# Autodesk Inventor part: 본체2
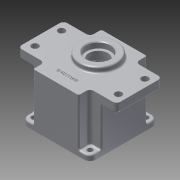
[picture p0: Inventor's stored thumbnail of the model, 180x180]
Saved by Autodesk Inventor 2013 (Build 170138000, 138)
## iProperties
Created: 2015-07
Part Number: 본체2
Material: 알루미늄 6061
Document SubType Name: Modeling
Designer: user
Density: 2.71 g/cm^3
Mass: 706.146 g
Surface Area: 672.799 cm^2
Volume: 260.571 cm^3
Author: user
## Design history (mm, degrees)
sketch "스케치1"
  geometry: L1 (-65, -30)-(65, -30); L2 (65, -30)-(65, 30); L3 (65, 30)-(-65, 30); L4 (-65, 30)-(-65, -30); L5 (-65, -30)-(65, 30); L6 (65, -30)-(-65, 30); 1 further point
  constraints: 12 end point, 2 midpoint, 2 parallel, 1 horizontal, 1 perpendicular
  dimensions: "d0" = 130 distance of L3.end L2.end; "d1" = 60 distance of L2.end L1.end
extrude "돌출1" new body sketch "스케치1" distance "d2" = 12; taper "d3" = 0 deg
sketch "스케치2"
  geometry: L1 (-30, -45)-(30, -45); L2 (30, -45)-(30, 45); L3 (30, 45)-(-30, 45); L4 (-30, 45)-(-30, -45); L5 (-30, -45)-(30, 45); L6 (30, -45)-(-30, 45); 1 further point
  constraints: 12 end point, 2 midpoint, 2 parallel, 1 horizontal, 1 perpendicular
  dimensions: "d4" = 60 distance of L3.end L2.end; "d5" = 90 distance of L2.end L1.end
extrude "돌출2" join sketch "스케치2" distance "d6" = 70; taper "d7" = 0 deg
sketch "스케치3"
  geometry: L1 (-30, -45)-(30, -45) reference; L2 (30, -45)-(30, 45) reference; L3 (30, 45)-(-30, 45) reference; L4 (-30, 45)-(-30, -45) reference; L5 (-45, -45)-(45, -45); L6 (45, -45)-(45, 45); L7 (45, 45)-(-45, 45); L8 (-45, 45)-(-45, -45); L9 (-45, -45)-(45, 45); L10 (45, -45)-(-45, 45); 1 further point
  constraints: 12 end point, 2 midpoint, 2 parallel, 1 horizontal, 1 perpendicular
  dimensions: "d8" = 90 distance of L7.end L6.end; "d9" = 90 distance of L6.end L5.end
extrude "돌출3" join sketch "스케치3" distance "d10" = 7; taper "d11" = 0 deg
fillet "모깎기1" dims "d12" = 5
fillet "모깎기2" dims "d13" = 8
sketch "스케치4"
  geometry: L1 (-45, -30)-(45, -30); L2 (45, -30)-(45, 30); L3 (45, 30)-(-45, 30); L4 (-45, 30)-(-45, -30); L5 (-45, -30)-(45, 30); L6 (45, -30)-(-45, 30); 1 further point
  constraints: 12 end point, 2 midpoint, 2 parallel, 1 horizontal, 1 perpendicular
  dimensions: "d14" = 90 distance of L3.end L2.end; "d15" = 60 distance of L2.end L1.end
extrude "돌출4" join sketch "스케치4" distance "d16" = 70; taper "d17" = 0 deg
fillet "모깎기3" dims "d18" = 5
fillet "모깎기4" dims "d19" = 2
fillet "모깎기5" dims "d20" = 2
fillet "모깎기6" dims "d21" = 2
sketch "스케치5"
  geometry: L1 (-37, -37)-(37, -37); L2 (37, -37)-(37, 37); L3 (37, 37)-(-37, 37); L4 (-37, 37)-(-37, -37); L5 (-37, -37)-(37, 37); L6 (37, -37)-(-37, 37); C1 r 3.5 at (37, 37); C2 r 3.5 at (37, -37); C3 r 3.5 at (-37, 37); C4 r 3.5 at (-37, -37); 1 further point
  constraints: 12 end point, 4 centre point, 4 coincident, 2 midpoint, 2 parallel, 1 horizontal, 1 perpendicular
  dimensions: "d22" = 74 distance of L3.end L2.end; "d23" = 74 distance of L2.end L1.end; "d24" = 7 diameter of C1; "d25" = 7 diameter of C2; "d26" = 7 diameter of C3; "d27" = 7 diameter of C4
extrude "돌출5" cut sketch "스케치5" distance "d28" = 70; taper "d29" = 0 deg
sketch "스케치6"
  geometry: L1 (-55, -17.5)-(55, -17.5); L2 (55, -17.5)-(55, 17.5); L3 (55, 17.5)-(-55, 17.5); L4 (-55, 17.5)-(-55, -17.5); L5 (-55, -17.5)-(55, 17.5); L6 (55, -17.5)-(-55, 17.5); C1 r 4.5 at (55, 17.5); C2 r 4.5 at (55, -17.5); C3 r 4.5 at (-55, -17.5); C4 r 4.5 at (-55, 17.5); 1 further point
  constraints: 12 end point, 4 centre point, 4 coincident, 2 midpoint, 2 parallel, 1 horizontal, 1 perpendicular
  dimensions: "d30" = 110 distance of L3.end L2.end; "d31" = 35 distance of L2.end L1.end; "d32" = 9 diameter of C1; "d33" = 9 diameter of C2; "d34" = 9 diameter of C3; "d35" = 9 diameter of C4
extrude "돌출6" cut sketch "스케치6" distance "d36" = 20; taper "d37" = 0 deg
sketch "스케치7"
  geometry: C1 r 40 at (0, 0); 1 further point
  constraints: 1 centre point, 1 coincident
  dimensions: "d38" = 80 diameter of C1
extrude "돌출7" cut sketch "스케치7" distance "d39" = 9; taper "d40" = 0 deg
sketch "스케치8"
  geometry: C1 r 40 at (0, 0) reference; C2 r 39 at (0, 0)
  constraints: 1 centre point, 1 coincident
  dimensions: "d41" = 78 diameter of C2
extrude "돌출8" cut sketch "스케치8" distance "d42" = 52; taper "d43" = 0 deg
sketch "스케치10"
  geometry: L1 (-45, -70)-(-45, 0) reference; L2 (-45, 0)-(45, 0) reference; L3 (45, 0)-(45, -70) reference; L4 (45, -70)-(40, -70) reference; L5 (40, -70)-(40, -61) reference; L6 (40, -61)-(39, -61) reference; L7 (39, -61)-(39, -9) reference; L8 (39, -9)-(-39, -9) reference; L9 (-39, -9)-(-39, -61) reference; L10 (-39, -61)-(-40, -61) reference; L11 (-40, -61)-(-40, -70) reference; L12 (-40, -70)-(-45, -70) reference; L13 (0, 0)-(11, 0); L14 (0, 0)-(-20, 0); L15 (11, 0)-(11, -16); L16 (11, 0)-(11, 7); L17 (-20, 0)-(-20, -16); L18 (27, 7)-(36, 7); L19 (36, 7)-(36, -5); L20 (36, -5)-(31.5, -5); L21 (31.5, -5)-(31.5, -16); L22 (31.5, -16)-(28.5, -16); L23 (28.5, -16)-(28.5, -6); L24 (28.5, -6)-(23.5, -6); L25 (23.5, -6)-(23.5, -1); L26 (23.5, -1)-(27, -1); L27 (27, -1)-(27, 7); L28 (-20, -16)-(-6, -16); L29 (-6, -16)-(-6, 0); L30 (-6, 0)-(-20, 0)
  constraints: 36 end point, 7 parallel, 7 perpendicular, 3 point on line, 2 collinear
  dimensions: "d44" = 11 distance of L13.start L13.end; "d45" = 20 distance of L13.start L14.end; "d46" = 16 distance of L13.end L15.end; "d47" = 7 distance of L13.end L16.end; "d48" = 16 distance of L14.end L17.end; "d49" = 32 diameter of L27 L15; "d50" = 25 diameter of L25 L15; "d51" = 35 diameter of L23 L15; "d52" = 41 diameter of L21 L15; "d53" = 50 diameter of L19 L15; "d54" = 7 distance between parallel lines of L2 L18; "d55" = 7 distance between parallel lines of L8 L22; "d56" = 8 distance of L26.end L18.start; "d57" = 5 distance of L24.end L25.end; "d58" = 4 distance between parallel lines of L8 L20; "d59" = 14 distance of L17.end L28.end
  node "절단 모서리 투영1"
revolve "회전1" stored, may be unused: angle "d60" = 90 deg
revolve "회전2" stored, may be unused: angle "d61" = 90 deg
sketch "스케치11"
  geometry: C1 r 17.5 at (0, 0); C2 r 12.5 at (0, 0); A1 r 17.5 centre (0, 0) between (2.777, -17.278) and (-2.777, -17.278) reference; A2 r 14 centre (0, -31) between (2.777, -17.278) and (-2.777, -17.278) reference; A3 r 20.5 centre (0, 0) between (7.402, -19.117) and (-7.402, -19.117) reference; 1 further point
  constraints: 2 centre point, 2 coincident, 1 concentric
  dimensions: "d62" = 25 diameter of C2
extrude "돌출10" cut sketch "스케치11" distance "d65" = 10; taper "d66" = 0 deg
extrude "돌출11" cut sketch "스케치11" distance "d67" = 50; taper "d68" = 0 deg
fillet "모깎기7" dims "d69" = 2
chamfer "모따기1" distance "d70" = 1; stored, may be unused: second distance "d71" = 2, angle "d72" = 45 deg
hole "구멍1" diameter "d75" = 19; stored, may be unused: countersink angle "d79" = 90 deg, drill point angle "d81" = 0 deg; dims "d73" = 10, "d74" = 10, "d76" = 6, "d77" = 22, "d78" = 7, "d80" = 8
chamfer "모따기2" distance "d82" = 1; stored, may be unused: second distance "d83" = 2, angle "d84" = 45 deg
fillet "모깎기8" dims "d85" = 2
fillet "모깎기10" dims "d121" = 2, "d122" = 3
node "작업 평면2"
sketch "스케치12"
  geometry: L1 (45, 28)-(45, -28) reference; L2 (43, -30)-(35, -30) reference; L3 (30, -35)-(30, -43) reference; L4 (28, -45)-(-28, -45) reference; L5 (-30, -43)-(-30, -35) reference; L6 (-35, -30)-(-43, -30) reference; L7 (-45, -28)-(-45, 28) reference; L8 (-43, 30)-(-35, 30) reference; L9 (-30, 35)-(-30, 43) reference; L10 (-28, 45)-(28, 45) reference; L11 (30, 43)-(30, 35) reference; L12 (35, 30)-(43, 30) reference; L13 (0, 0)-(24.749, 24.749); L14 (0, 0)-(35, 0); L15 (24.603, 30.26)-(21.758, 27.415); L16 (30.26, 24.603)-(27.415, 21.758); L17 (5.657, 0)-(4.581, -1.076); C1 r 40 at (0, 0) reference; A1 r 39 centre (0, 0) between (30.26, 24.603) and (24.603, 30.26) reference; A2 r 2 centre (43, 28) between (45, 28) and (43, 30) reference; A3 r 2 centre (43, -28) between (43, -30) and (45, -28) reference; A4 r 5 centre (35, -35) between (35, -30) and (30, -35) reference; A5 r 2 centre (28, -43) between (28, -45) and (30, -43) reference; A6 r 2 centre (-28, -43) between (-30, -43) and (-28, -45) reference; A7 r 5 centre (-35, -35) between (-30, -35) and (-35, -30) reference; A8 r 2 centre (-43, -28) between (-45, -28) and (-43, -30) reference; A9 r 2 centre (-43, 28) between (-43, 30) and (-45, 28) reference; A10 r 5 centre (-35, 35) between (-35, 30) and (-30, 35) reference; A11 r 2 centre (-28, 43) between (-28, 45) and (-30, 43) reference; A12 r 2 centre (28, 43) between (30, 43) and (28, 45) reference; A13 r 5 centre (35, 35) between (30, 35) and (35, 30) reference; A14 r 35 centre (0, 0) between (24.749, 24.749) and (27.415, 21.758); A15 r 4 centre (24.749, 24.749) between (21.92, 27.577) and (27.577, 21.92); 2 further points
  constraints: 10 end point, 7 point on circle, 3 coincident, 3 point on line, 2 centre point, 2 parallel, 2 tangent, 1 equal length, 1 horizontal, 3 other
  dimensions: "d90" = 70 diameter of A14; "d91" = 45 deg angle of L14 L13; "d92" = 8 diameter of A15; "d95" = 4 distance from line of A1.centre L16
extrude "돌출12" join sketch "스케치12" distance "d96" = 55; taper "d97" = 0 deg
fillet "모깎기12" dims "d101" = 3.5
fillet "모깎기13" dims "d105" = 2
hole "구멍2" diameter "d108" = 3.459; stored, may be unused: countersink angle "d112" = 90 deg, drill point angle "d114" = 118 deg; dims "d106" = 10, "d107" = 10, "d109" = 12, "d110" = 22, "d111" = 7, "d113" = 15
sketch "스케치13"
  geometry: L1 (-28, -45)-(28, -45) reference; L2 (-30, -35)-(-30, -43) reference; L3 (0, -45)-(0, -30); 2 further points
  constraints: 2 end point, 1 coincident, 1 midpoint, 1 parallel, 1 other
  dimensions: "d118" = 15 distance of L3.start L3.end
feature "엠보싱1" sketch "스케치13" dims "d119" = 0.5, "d120" = 0
node "작업 평면3"
sketch "스케치14"
  geometry: C1 r 15.7 at (0, 0) reference; C2 r 16 at (0, 0); 1 further point
  constraints: 1 centre point, 1 coincident
  dimensions: "d123" = 32 diameter of C2
extrude "돌출13" cut sketch "스케치14" distance "d124" = 1; taper "d125" = 0 deg
sketch "스케치15"
  geometry: C1 r 15.7 at (0, 0) reference; C2 r 12.5 at (0, 0) reference; C3 r 16 at (0, 0); 1 further point
  constraints: 1 centre point, 1 coincident
  dimensions: "d126" = 32 diameter of C3
extrude "돌출14" cut sketch "스케치15" distance "d127" = 1; taper "d128" = 0 deg
fillet "모깎기14" dims "d129" = 0.3
node "솔리드1"
pattern_circular "원형 패턴1" dims angle "d99" = 360 deg
pattern_circular "원형 패턴2" dims angle "d103" = 360 deg
pattern_circular "원형 패턴3" dims angle "d116" = 360 deg
node "절단 모서리 투영2"
other parameters: "d89" = -9, "d93" = 4, "d94" = 8
